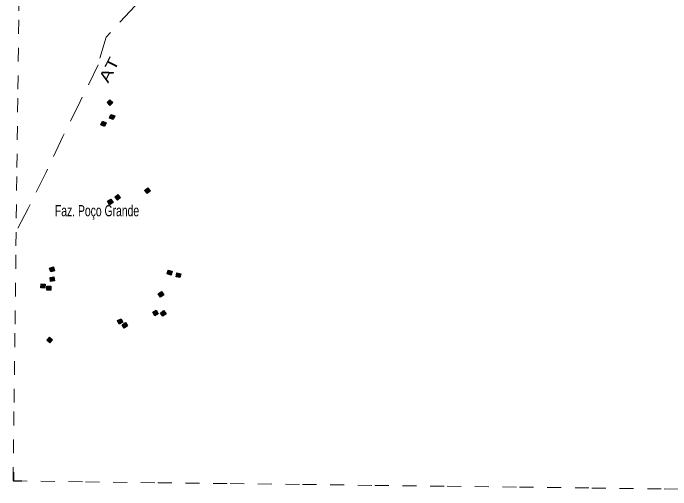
# Model space of a CAD drawing. Extents: x 679 to 705, y 7427.4 to 7455.4.
# Drawn here: x 679.037 to 683.784, y 7427.628 to 7431.066 of the extents above; entities that cross this region are included whole.
import ezdxf
from ezdxf.enums import TextEntityAlignment as Align

# ---------------------------------------------------------------- set-up
doc = ezdxf.new("R2010")
doc.units = 0
doc.header["$LTSCALE"] = 0.032
doc.linetypes.add('DOT_DASHED', pattern=[7.7, 5, -1.2, 0.3, -1.2])
doc.linetypes.add('SHORT_DASHED', pattern=[2.7, 1.5, -1.2])
for name, color, linetype, lineweight in [('2', 7, 'Continuous', 25), ('56', 7, 'DOT_DASHED', 13), ('58', 7, 'SHORT_DASHED', 13), ('63', 7, 'Continuous', 25)]:
    doc.layers.add(name, color=color, linetype=linetype, lineweight=lineweight)
doc.layers.add('61', color=7, linetype='Continuous')

msp = doc.modelspace()

# ---------------------------------------------------------------- hatches: boundary and pattern name
at = {"layer": '2'}
for points in [[(679.7355, 7430.4413), (679.756, 7430.4208), (679.7355, 7430.4003), (679.715, 7430.4208)], [(679.7702, 7430.3255), (679.7601, 7430.2983), (679.7329, 7430.3084), (679.743, 7430.3356)], [(679.683, 7430.2864), (679.7095, 7430.2747), (679.6978, 7430.2482), (679.6713, 7430.2599)], [(680.0082, 7429.805), (680.0274, 7429.7832), (680.0055, 7429.764), (679.9864, 7429.7859)], [(679.7431, 7429.724), (679.758, 7429.6991), (679.7331, 7429.6843), (679.7182, 7429.7092)], [(679.7918, 7429.7584), (679.8117, 7429.7373), (679.7906, 7429.7174), (679.7707, 7429.7385)], [(679.328, 7429.2353), (679.3365, 7429.2077), (679.3087, 7429.1991), (679.3004, 7429.227)], [(680.1849, 7429.2046), (680.1766, 7429.1768), (680.1488, 7429.1851), (680.1571, 7429.2129)], [(679.3321, 7429.1643), (679.3364, 7429.1356), (679.3077, 7429.1313), (679.3034, 7429.16)], [(680.2478, 7429.1864), (680.241, 7429.1582), (680.2128, 7429.165), (680.2196, 7429.1932)], [(679.2674, 7429.1109), (679.2658, 7429.0819), (679.2368, 7429.0835), (679.2384, 7429.1125)], [(679.3086, 7429.0972), (679.3093, 7429.0682), (679.2803, 7429.0675), (679.2796, 7429.0965)], [(680.1074, 7429.0577), (680.1243, 7429.0341), (680.1008, 7429.0172), (680.0838, 7429.0407)], [(680.084, 7428.898), (680.059, 7428.8833), (680.0443, 7428.9083), (680.0693, 7428.923)], [(680.1227, 7428.9203), (680.1407, 7428.8975), (680.1179, 7428.8795), (680.0999, 7428.9023)], [(679.8283, 7428.836), (679.802, 7428.8236), (679.7896, 7428.85), (679.8159, 7428.8622)], [(679.8475, 7428.8348), (679.8637, 7428.8108), (679.8397, 7428.7945), (679.8235, 7428.8185)], [(679.2995, 7428.7294), (679.3215, 7428.7105), (679.3026, 7428.6885), (679.2806, 7428.7074)]]:
    msp.add_hatch(color=256, dxfattribs=at).paths.add_polyline_path(points)

# ---------------------------------------------------------------- linework, layer by layer
for points in [[(679.7355, 7430.4413), (679.756, 7430.4208), (679.7355, 7430.4003), (679.715, 7430.4208)], [(679.7702, 7430.3255), (679.7601, 7430.2983), (679.7329, 7430.3084), (679.743, 7430.3356)], [(679.683, 7430.2864), (679.7095, 7430.2747), (679.6978, 7430.2482), (679.6713, 7430.2599)], [(680.0082, 7429.805), (680.0274, 7429.7832), (680.0055, 7429.764), (679.9864, 7429.7859)], [(679.7431, 7429.724), (679.758, 7429.6991), (679.7331, 7429.6843), (679.7182, 7429.7092)], [(679.7918, 7429.7584), (679.8117, 7429.7373), (679.7906, 7429.7174), (679.7707, 7429.7385)], [(679.328, 7429.2353), (679.3365, 7429.2077), (679.3087, 7429.1991), (679.3004, 7429.227)], [(680.1849, 7429.2046), (680.1766, 7429.1768), (680.1488, 7429.1851), (680.1571, 7429.2129)], [(679.3321, 7429.1643), (679.3364, 7429.1356), (679.3077, 7429.1313), (679.3034, 7429.16)], [(680.2478, 7429.1864), (680.241, 7429.1582), (680.2128, 7429.165), (680.2196, 7429.1932)], [(679.2674, 7429.1109), (679.2658, 7429.0819), (679.2368, 7429.0835), (679.2384, 7429.1125)], [(679.3086, 7429.0972), (679.3093, 7429.0682), (679.2803, 7429.0675), (679.2796, 7429.0965)], [(680.1074, 7429.0577), (680.1243, 7429.0341), (680.1008, 7429.0172), (680.0838, 7429.0407)], [(680.084, 7428.898), (680.059, 7428.8833), (680.0443, 7428.9083), (680.0693, 7428.923)], [(680.1227, 7428.9203), (680.1407, 7428.8975), (680.1179, 7428.8795), (680.0999, 7428.9023)], [(679.8283, 7428.836), (679.802, 7428.8236), (679.7896, 7428.85), (679.8159, 7428.8622)], [(679.8475, 7428.8348), (679.8637, 7428.8108), (679.8397, 7428.7945), (679.8235, 7428.8185)], [(679.2995, 7428.7294), (679.3215, 7428.7105), (679.3026, 7428.6885), (679.2806, 7428.7074)]]:
    msp.add_lwpolyline(points, close=True, dxfattribs=at)
at = {"layer": '56'}
for points in [[(681.1789, 7432.1929), (681.0842, 7432.1347), (680.9359, 7432.0959), (680.6351, 7431.9829), (680.2832, 7431.5576), (680.1018, 7431.3382), (679.9169, 7431.1174), (679.7096, 7430.8935)], [(679.7096, 7430.8935), (679.6499, 7430.6936), (679.5217, 7430.4294), (679.3964, 7430.1758), (679.2747, 7429.9191), (679.1465, 7429.6564), (679.0591, 7429.4936)]]:
    msp.add_lwpolyline(points, dxfattribs=at)
at = {"layer": '58'}
for points in [[(679.0374, 7427.6915), (679.0442, 7428.2565), (679.051, 7428.8215), (679.0578, 7429.3865), (679.0646, 7429.9515), (679.0714, 7430.5166), (679.0782, 7431.0816), (679.085, 7431.6466), (679.0918, 7432.2116), (679.0986, 7432.7766), (679.1054, 7433.3416), (679.1122, 7433.9066), (679.119, 7434.4716), (679.1258, 7435.0366), (679.1326, 7435.6016), (679.1394, 7436.1666), (679.1462, 7436.7316), (679.153, 7437.2966), (679.1598, 7437.8616), (679.1666, 7438.4266), (679.1734, 7438.9916), (679.1802, 7439.5566), (679.1869, 7440.1216)], [(679.0374, 7427.6915), (679.5595, 7427.6852), (680.0816, 7427.6789), (680.6036, 7427.6726), (681.1257, 7427.6662), (681.6478, 7427.6598), (682.1699, 7427.6534), (682.692, 7427.647), (683.2141, 7427.6406), (683.7362, 7427.6341), (684.2583, 7427.6276)]]:
    msp.add_lwpolyline(points, dxfattribs=at)
at = {"layer": '63'}
msp.add_lwpolyline([(679.0399, 7427.7548), (679.0399, 7427.6932), (679.1006, 7427.6932)], dxfattribs=at)

# ---------------------------------------------------------------- texts
at = {"layer": '61', "width": 1.35}
msp.add_text('AT', height=0.08, rotation=63.186, dxfattribs=at).set_placement((679.7649, 7430.639), align=Align.CENTER)
at = {"layer": '61', "width": 0.7}
msp.add_text('Faz. Poço Grande', height=0.08, dxfattribs=at).set_placement((679.3388, 7429.6009))

doc.saveas('drawing.dxf')
